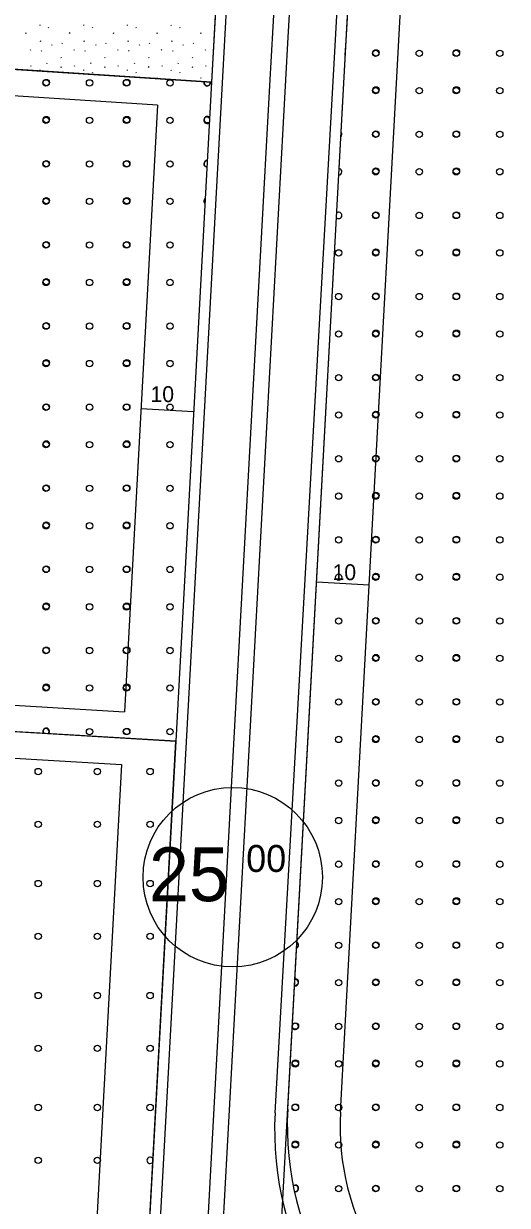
# Model space of a CAD drawing. Extents: x 419396 to 421519, y 4453567 to 4456767.
# Drawn here: x 420849.4 to 420941, y 4455339.6 to 4455563.3 of the extents above; entities that cross this region are included whole.
import ezdxf

# ---------------------------------------------------------------- set-up
doc = ezdxf.new("R2010")
doc.units = 0
for name, color, linetype in [('0_KADASTRO', 7, 'Continuous'), ('@PL', 7, 'Continuous'), ('ADAKENARI1000', 7, 'Continuous'), ('F_YAPI_YAKLAŞMA', 7, 'Continuous'), ('KALDIRIM', 7, 'Continuous'), ('Level 33', 7, 'Continuous'), ('Level 41', 7, 'Continuous')]:
    doc.layers.add(name, color=color, linetype=linetype)

msp = doc.modelspace()

# ---------------------------------------------------------------- linework, layer by layer
at = {"layer": '0_KADASTRO'}
for points in [[(420545.42, 4455447.04), (420561.03, 4455696.59), (420608.27, 4455685.53), (420614.84, 4455734.09), (420621.11, 4455745.07), (420621.38, 4455786.21), (420636.29, 4455823.29), (420701.58, 4455861.23), (420708.62, 4455863.92), (420715.79, 4455864.57), (420723.78, 4455862.78), (420730.13, 4455859.19), (420735, 4455853.4), (420771.9, 4455797.51), (420787.06, 4455778.4), (420884.04, 4455668.02), (420888.93, 4455658.72), (420890.16, 4455653.06), (420890.46, 4455645.52), (420886.58, 4455581.52), (420884.98, 4455552.19), (420718.56, 4455563.04), (420710.4, 4455437.34), (420549.3, 4455446.81)], [(420710.4, 4455437.34), (420718.56, 4455563.04), (420884.98, 4455552.19), (420878.18, 4455427.47)]]:
    msp.add_lwpolyline(points, close=True, dxfattribs=at)
for points in [[(420889.85, 4455182.58), (420910.45, 4455560.12), (420915.41, 4455643.95), (420915.58, 4455650.46), (420914.6, 4455657.96), (420913.46, 4455663.67), (420911.34, 4455669.86), (420909.75, 4455673.13), (420911.57, 4455679.67), (420935.86, 4455688.27), (420947.76, 4455688.77), (420960.08, 4455684.75), (420973.09, 4455678.47), (421003.12, 4455663.97), (421028.47, 4455648.45), (421040.23, 4455638.43), (421137.17, 4455559.09), (421140.51, 4455550.95), (421136.04, 4455509.5), (421128.22, 4455437.47), (421062.99, 4455307.75)], [(420652.36, 4454984), (420665.76, 4454988.47), (420707.29, 4455006.2), (420751.48, 4455032.99), (420769.07, 4455051.2), (420804.89, 4455072.7), (420840.78, 4455094.99), (420847.65, 4455100.22), (420853.39, 4455106.67), (420857.79, 4455114.1), (420861.99, 4455130.83), (420878.18, 4455427.47), (420710.4, 4455437.34), (420549.3, 4455446.81)]]:
    msp.add_lwpolyline(points, dxfattribs=at)
at = {"layer": '@PL'}
msp.add_circle((420888.98, 4455401.72), 17, dxfattribs=at)
at = {"layer": 'ADAKENARI1000'}
for p, q in [((420899.41, 4455357.78), (420912.26, 4455593.26)), ((420886.58, 4455581.52), (420884.98, 4455552.19)), ((420884.98, 4455552.19), (420718.56, 4455563.04)), ((420910.3, 4455557.31), (420910.45, 4455560.12)), ((420884.98, 4455552.19), (420878.18, 4455427.47)), ((420710.4, 4455437.34), (420878.18, 4455427.47)), ((420878.18, 4455427.47), (420861.99, 4455130.83))]:
    msp.add_line(p, q, dxfattribs=at)
msp.add_arc((420957.24, 4455354.62), 57.92, 176.8768, 245.103, dxfattribs=at)
at = {"layer": 'F_YAPI_YAKLAŞMA'}
for p, q in [((420909.39, 4455357.23), (420922.2, 4455591.93)), ((420874.73, 4455547.85), (420723.23, 4455557.73)), ((420874.73, 4455547.85), (420868.47, 4455433.05)), ((420871.6, 4455490.45), (420881.58, 4455489.9)), ((420914.84, 4455457), (420904.85, 4455457.54)), ((420715.72, 4455442.04), (420868.47, 4455433.05)), ((420710.11, 4455432.35), (420867.92, 4455423.06)), ((420867.92, 4455423.06), (420852.06, 4455132.33))]:
    msp.add_line(p, q, dxfattribs=at)
msp.add_arc((420957.24, 4455354.62), 47.92, 176.8768, 245.103, dxfattribs=at)
at = {"layer": 'KALDIRIM'}
for p, q in [((420899.47, 4455560.74), (420901.54, 4455595.74)), ((420908.45, 4455560.23), (420910.48, 4455594.52)), ((420888.58, 4455581.4), (420886.98, 4455552.08)), ((420897.56, 4455580.88), (420895.96, 4455551.59)), ((420885.7, 4455308.35), (420899.47, 4455560.74)), ((420897.01, 4455357.08), (420908.45, 4455560.23)), ((420886.98, 4455552.08), (420880.17, 4455427.36)), ((420895.96, 4455551.59), (420889.16, 4455426.87)), ((420880.17, 4455427.36), (420863.98, 4455130.53)), ((420889.16, 4455426.87), (420882.25, 4455300.18))]:
    msp.add_line(p, q, dxfattribs=at)
msp.add_arc((420956.92, 4455353.76), 60, 176.8275, 245.103, dxfattribs=at)
at = {"layer": 'Level 33'}
for centre in [(420916.07, 4455557.69), (420916.13, 4455557.76), (420924.33, 4455557.69), (420931.33, 4455557.69), (420931.39, 4455557.76), (420939.59, 4455557.69), (420853.59, 4455552.09), (420853.65, 4455552.15), (420861.85, 4455552.09), (420868.85, 4455552.09), (420868.91, 4455552.15), (420877.11, 4455552.09), (420916.07, 4455550.61), (420916.13, 4455550.76), (420924.33, 4455550.61), (420931.33, 4455550.61), (420931.39, 4455550.76), (420939.59, 4455550.61), (420853.59, 4455545), (420853.65, 4455545.15), (420861.85, 4455545), (420868.85, 4455545), (420868.91, 4455545.15), (420877.11, 4455545), (420916.07, 4455542.34), (420916.13, 4455542.41), (420924.33, 4455542.34), (420931.33, 4455542.34), (420931.39, 4455542.41), (420939.59, 4455542.34), (420853.59, 4455536.74), (420853.65, 4455536.8), (420861.85, 4455536.74), (420868.85, 4455536.74), (420868.91, 4455536.8), (420877.11, 4455536.74), (420916.07, 4455535.26), (420916.13, 4455535.41), (420924.33, 4455535.26), (420931.33, 4455535.26), (420931.39, 4455535.41), (420939.59, 4455535.26), (420853.59, 4455529.65), (420853.65, 4455529.8), (420861.85, 4455529.65), (420868.85, 4455529.65), (420868.91, 4455529.8), (420877.11, 4455529.65), (420916.07, 4455526.99), (420916.13, 4455527.05), (420924.33, 4455526.99), (420931.33, 4455526.99), (420931.39, 4455527.05), (420939.59, 4455526.99), (420853.59, 4455521.39), (420853.65, 4455521.45), (420861.85, 4455521.39), (420868.85, 4455521.39), (420868.91, 4455521.45), (420877.11, 4455521.39), (420909.07, 4455519.9), (420916.07, 4455519.9), (420916.13, 4455520.05), (420924.33, 4455519.9), (420931.33, 4455519.9), (420931.39, 4455520.05), (420939.59, 4455519.9), (420853.59, 4455514.3), (420853.65, 4455514.45), (420861.85, 4455514.3), (420868.85, 4455514.3), (420868.91, 4455514.45), (420877.11, 4455514.3), (420909.07, 4455511.64), (420916.07, 4455511.64), (420916.13, 4455511.7), (420924.33, 4455511.64), (420931.33, 4455511.64), (420931.39, 4455511.7), (420939.59, 4455511.64), (420853.59, 4455506.03), (420853.65, 4455506.1), (420861.85, 4455506.03), (420868.85, 4455506.03), (420868.91, 4455506.1), (420877.11, 4455506.03), (420909.07, 4455504.55), (420916.07, 4455504.55), (420916.13, 4455504.7), (420924.33, 4455504.55), (420931.33, 4455504.55), (420931.39, 4455504.7), (420939.59, 4455504.55), (420853.59, 4455498.95), (420853.65, 4455499.1), (420861.85, 4455498.95), (420868.85, 4455498.95), (420868.91, 4455499.1), (420877.11, 4455498.95), (420909.07, 4455496.29), (420916.07, 4455496.29), (420916.13, 4455496.35), (420924.33, 4455496.29), (420931.33, 4455496.29), (420931.39, 4455496.35), (420939.59, 4455496.29), (420853.59, 4455490.68), (420853.65, 4455490.74), (420861.85, 4455490.68), (420868.85, 4455490.68), (420868.91, 4455490.74), (420877.11, 4455490.68), (420909.07, 4455489.2), (420916.07, 4455489.2), (420916.13, 4455489.35), (420924.33, 4455489.2), (420931.33, 4455489.2), (420931.39, 4455489.35), (420939.59, 4455489.2), (420853.59, 4455483.59), (420853.65, 4455483.74), (420861.85, 4455483.59), (420868.85, 4455483.59), (420868.91, 4455483.74), (420877.11, 4455483.59), (420909.07, 4455480.93), (420916.07, 4455480.93), (420916.13, 4455481), (420924.33, 4455480.93), (420931.33, 4455480.93), (420931.39, 4455481), (420939.59, 4455480.93), (420853.59, 4455475.33), (420853.65, 4455475.39), (420861.85, 4455475.33), (420868.85, 4455475.33), (420868.91, 4455475.39), (420877.11, 4455475.33), (420916.13, 4455474), (420931.39, 4455474), (420909.07, 4455473.85), (420916.07, 4455473.85), (420924.33, 4455473.85), (420931.33, 4455473.85), (420939.59, 4455473.85), (420853.59, 4455468.24), (420853.65, 4455468.39), (420861.85, 4455468.24), (420868.85, 4455468.24), (420868.91, 4455468.39), (420877.11, 4455468.24), (420909.07, 4455465.58), (420916.07, 4455465.58), (420916.13, 4455465.65), (420924.33, 4455465.58), (420931.33, 4455465.58), (420931.39, 4455465.65), (420939.59, 4455465.58), (420853.59, 4455459.98), (420853.65, 4455460.04), (420861.85, 4455459.98), (420868.85, 4455459.98), (420868.91, 4455460.04), (420877.11, 4455459.98), (420909.07, 4455458.5), (420916.07, 4455458.5), (420916.13, 4455458.65), (420924.33, 4455458.5), (420931.33, 4455458.5), (420931.39, 4455458.65), (420939.59, 4455458.5), (420853.59, 4455452.89), (420853.65, 4455453.04), (420861.85, 4455452.89), (420868.85, 4455452.89), (420868.91, 4455453.04), (420877.11, 4455452.89), (420909.07, 4455450.23), (420916.07, 4455450.23), (420916.13, 4455450.29), (420924.33, 4455450.23), (420931.33, 4455450.23), (420931.39, 4455450.29), (420939.59, 4455450.23), (420853.59, 4455444.63), (420853.65, 4455444.69), (420861.85, 4455444.63), (420868.85, 4455444.63), (420868.91, 4455444.69), (420877.11, 4455444.63), (420909.07, 4455443.14), (420916.07, 4455443.14), (420916.13, 4455443.29), (420924.33, 4455443.14), (420931.33, 4455443.14), (420931.39, 4455443.29), (420939.59, 4455443.14), (420853.59, 4455437.54), (420853.65, 4455437.69), (420861.85, 4455437.54), (420868.85, 4455437.54), (420868.91, 4455437.69), (420877.11, 4455437.54), (420909.07, 4455434.88), (420916.07, 4455434.88), (420916.13, 4455434.94), (420924.33, 4455434.88), (420931.33, 4455434.88), (420931.39, 4455434.94), (420939.59, 4455434.88), (420861.85, 4455429.27), (420868.85, 4455429.27), (420868.91, 4455429.34), (420877.11, 4455429.27), (420909.07, 4455427.79), (420916.07, 4455427.79), (420916.13, 4455427.94), (420924.33, 4455427.79), (420931.33, 4455427.79), (420931.39, 4455427.94), (420939.59, 4455427.79), (420852.12, 4455421.72), (420863.33, 4455421.72), (420873.33, 4455421.72), (420909.07, 4455419.53), (420916.07, 4455419.53), (420916.13, 4455419.59), (420924.33, 4455419.53), (420931.33, 4455419.53), (420931.39, 4455419.59), (420939.59, 4455419.53), (420852.12, 4455411.72), (420863.33, 4455411.72), (420873.33, 4455411.72), (420909.07, 4455412.44), (420916.07, 4455412.44), (420916.13, 4455412.59), (420924.33, 4455412.44), (420931.33, 4455412.44), (420931.39, 4455412.59), (420939.59, 4455412.44), (420909.07, 4455404.17), (420916.07, 4455404.17), (420916.13, 4455404.24), (420924.33, 4455404.17), (420931.33, 4455404.17), (420931.39, 4455404.24), (420939.59, 4455404.17), (420852.12, 4455400.52), (420863.33, 4455400.52), (420873.33, 4455400.52), (420909.07, 4455397.09), (420916.07, 4455397.09), (420916.13, 4455397.24), (420924.33, 4455397.09), (420931.33, 4455397.09), (420931.39, 4455397.24), (420939.59, 4455397.09), (420852.12, 4455390.52), (420863.33, 4455390.52), (420873.33, 4455390.52), (420909.07, 4455388.82), (420916.07, 4455388.82), (420916.13, 4455388.89), (420924.33, 4455388.82), (420931.33, 4455388.82), (420931.39, 4455388.89), (420939.59, 4455388.82), (420909.07, 4455381.74), (420916.07, 4455381.74), (420916.13, 4455381.89), (420924.33, 4455381.74), (420931.33, 4455381.74), (420931.39, 4455381.89), (420939.59, 4455381.74), (420852.12, 4455379.32), (420863.33, 4455379.32), (420873.33, 4455379.32), (420900.87, 4455373.53), (420909.07, 4455373.47), (420916.07, 4455373.47), (420916.13, 4455373.53), (420924.33, 4455373.47), (420931.33, 4455373.47), (420931.39, 4455373.53), (420939.59, 4455373.47), (420852.12, 4455369.32), (420863.33, 4455369.32), (420873.33, 4455369.32), (420900.82, 4455366.38), (420900.87, 4455366.53), (420909.07, 4455366.38), (420916.07, 4455366.38), (420916.13, 4455366.53), (420924.33, 4455366.38), (420931.33, 4455366.38), (420931.39, 4455366.53), (420939.59, 4455366.38), (420852.12, 4455358.12), (420863.33, 4455358.12), (420873.33, 4455358.12), (420900.82, 4455358.12), (420900.87, 4455358.18), (420909.07, 4455358.12), (420916.07, 4455358.12), (420916.13, 4455358.18), (420924.33, 4455358.12), (420931.33, 4455358.12), (420931.39, 4455358.18), (420939.59, 4455358.12), (420900.82, 4455351.03), (420900.87, 4455351.18), (420909.07, 4455351.03), (420916.07, 4455351.03), (420916.13, 4455351.18), (420924.33, 4455351.03), (420931.33, 4455351.03), (420931.39, 4455351.18), (420939.59, 4455351.03), (420852.12, 4455348.12), (420863.33, 4455348.12), (420909.07, 4455342.77), (420916.07, 4455342.77), (420916.13, 4455342.83), (420924.33, 4455342.77), (420931.33, 4455342.77), (420931.39, 4455342.83), (420939.59, 4455342.77)]:
    msp.add_circle(centre, 0.6, dxfattribs=at)
for centre, start, end in [((420884.11, 4455552.09), 160.9712, 11.5689), ((420884.16, 4455552.15), 167.4763, 5.0639), ((420884.11, 4455545), 34.0055, 319.7499), ((420884.16, 4455545.15), 40.954, 312.8014), ((420909.07, 4455542.34), 309.1806, 44.573), ((420884.11, 4455536.74), 84.1802, 269.5752), ((420884.16, 4455536.8), 89.1573, 264.5981), ((420909.07, 4455535.26), 268.5652, 85.1884), ((420884.11, 4455529.65), 123.4869, 230.2684), ((420884.16, 4455529.8), 129.3498, 224.4055), ((420909.07, 4455526.99), 220.7419, 133.0117), ((420853.59, 4455429.27), 319.9465, 213.3183), ((420853.65, 4455429.34), 311.5715, 221.6933), ((420900.82, 4455388.82), 295.1672, 58.5864), ((420900.87, 4455388.89), 289.6512, 64.1024), ((420900.82, 4455381.74), 257.109, 96.6446), ((420900.87, 4455381.89), 252.4863, 101.2673), ((420900.82, 4455373.47), 199.937, 153.8166), ((420873.33, 4455348.12), 26.8047, 326.9489), ((420900.87, 4455342.83), 248.6374, 134.9124), ((420900.82, 4455342.77), 256.1113, 127.534)]:
    msp.add_arc(centre, 0.6, start, end, dxfattribs=at)
at = {"layer": 'Level 41'}
for p, q in [((420852.4, 4455563.08), (420852.41, 4455562.92)), ((420854.03, 4455562.61), (420854.1, 4455562.5)), ((420860.69, 4455563.08), (420860.71, 4455562.92)), ((420862.32, 4455562.61), (420862.39, 4455562.5)), ((420868.98, 4455563.08), (420869, 4455562.92)), ((420870.61, 4455562.61), (420870.68, 4455562.5)), ((420877.28, 4455563.08), (420877.29, 4455562.92)), ((420878.91, 4455562.61), (420878.98, 4455562.5)), ((420885.57, 4455563.08), (420885.57, 4455563.05)), ((420849.79, 4455561.46), (420849.86, 4455561.62)), ((420852.56, 4455559.93), (420852.63, 4455560.09)), ((420856.64, 4455559.52), (420856.72, 4455559.68)), ((420858.08, 4455561.46), (420858.15, 4455561.62)), ((420860.85, 4455559.93), (420860.92, 4455560.09)), ((420864.94, 4455559.52), (420865.01, 4455559.68)), ((420866.38, 4455561.46), (420866.45, 4455561.62)), ((420869.15, 4455559.93), (420869.22, 4455560.09)), ((420873.23, 4455559.52), (420873.3, 4455559.68)), ((420874.67, 4455561.46), (420874.74, 4455561.62)), ((420877.44, 4455559.93), (420877.51, 4455560.09)), ((420881.52, 4455559.52), (420881.59, 4455559.68)), ((420882.96, 4455561.46), (420883.03, 4455561.62)), ((420850.57, 4455558.39), (420850.64, 4455558.28)), ((420852.67, 4455558.19), (420852.74, 4455558.09)), ((420854.66, 4455559.32), (420854.73, 4455559.21)), ((420858.86, 4455558.39), (420858.94, 4455558.28)), ((420860.96, 4455558.19), (420861.03, 4455558.09)), ((420862.95, 4455559.32), (420863.02, 4455559.21)), ((420867.16, 4455558.39), (420867.23, 4455558.28)), ((420869.26, 4455558.19), (420869.33, 4455558.09)), ((420871.24, 4455559.32), (420871.31, 4455559.21)), ((420875.45, 4455558.39), (420875.52, 4455558.28)), ((420877.55, 4455558.19), (420877.62, 4455558.09)), ((420879.54, 4455559.32), (420879.61, 4455559.21)), ((420883.74, 4455558.39), (420883.81, 4455558.28)), ((420850.64, 4455555.36), (420850.71, 4455555.25)), ((420853.77, 4455555.74), (420853.84, 4455555.9)), ((420856.41, 4455556.93), (420856.48, 4455556.83)), ((420856.47, 4455555.01), (420856.54, 4455555.17)), ((420858.93, 4455555.36), (420859, 4455555.25)), ((420862.06, 4455555.74), (420862.13, 4455555.9)), ((420864.7, 4455556.93), (420864.77, 4455556.83)), ((420864.76, 4455555.01), (420864.83, 4455555.17)), ((420867.22, 4455555.36), (420867.3, 4455555.25)), ((420870.35, 4455555.74), (420870.42, 4455555.9)), ((420872.99, 4455556.93), (420873.07, 4455556.83)), ((420873.05, 4455555.01), (420873.12, 4455555.17)), ((420875.52, 4455555.36), (420875.59, 4455555.25)), ((420878.65, 4455555.74), (420878.72, 4455555.9)), ((420881.29, 4455556.93), (420881.36, 4455556.83)), ((420881.35, 4455555.01), (420881.42, 4455555.17)), ((420883.81, 4455555.36), (420883.88, 4455555.25)), ((420852.4, 4455554.57), (420852.41, 4455554.41)), ((420860.69, 4455554.57), (420860.71, 4455554.41)), ((420862.32, 4455554.1), (420862.39, 4455553.99)), ((420868.98, 4455554.57), (420869, 4455554.41)), ((420870.61, 4455554.1), (420870.68, 4455553.99)), ((420874.67, 4455552.95), (420874.74, 4455553.11)), ((420877.28, 4455554.57), (420877.29, 4455554.41)), ((420878.91, 4455554.1), (420878.98, 4455553.99)), ((420882.96, 4455552.95), (420883.03, 4455553.11))]:
    msp.add_line(p, q, dxfattribs=at)

# ---------------------------------------------------------------- texts
at = {"layer": '@PL'}
for s, height, p in [('25', 10.2, (420873.1, 4455397.17)), ('00', 5.1, (420891.53, 4455402.71))]:
    msp.add_text(s, height=height, dxfattribs=at).set_placement(p)
at = {"layer": 'F_YAPI_YAKLAŞMA'}
for p in [(420873.4, 4455491.66), (420907.9, 4455457.95)]:
    msp.add_text('10', height=3, dxfattribs=at).set_placement(p)

doc.saveas('drawing.dxf')
